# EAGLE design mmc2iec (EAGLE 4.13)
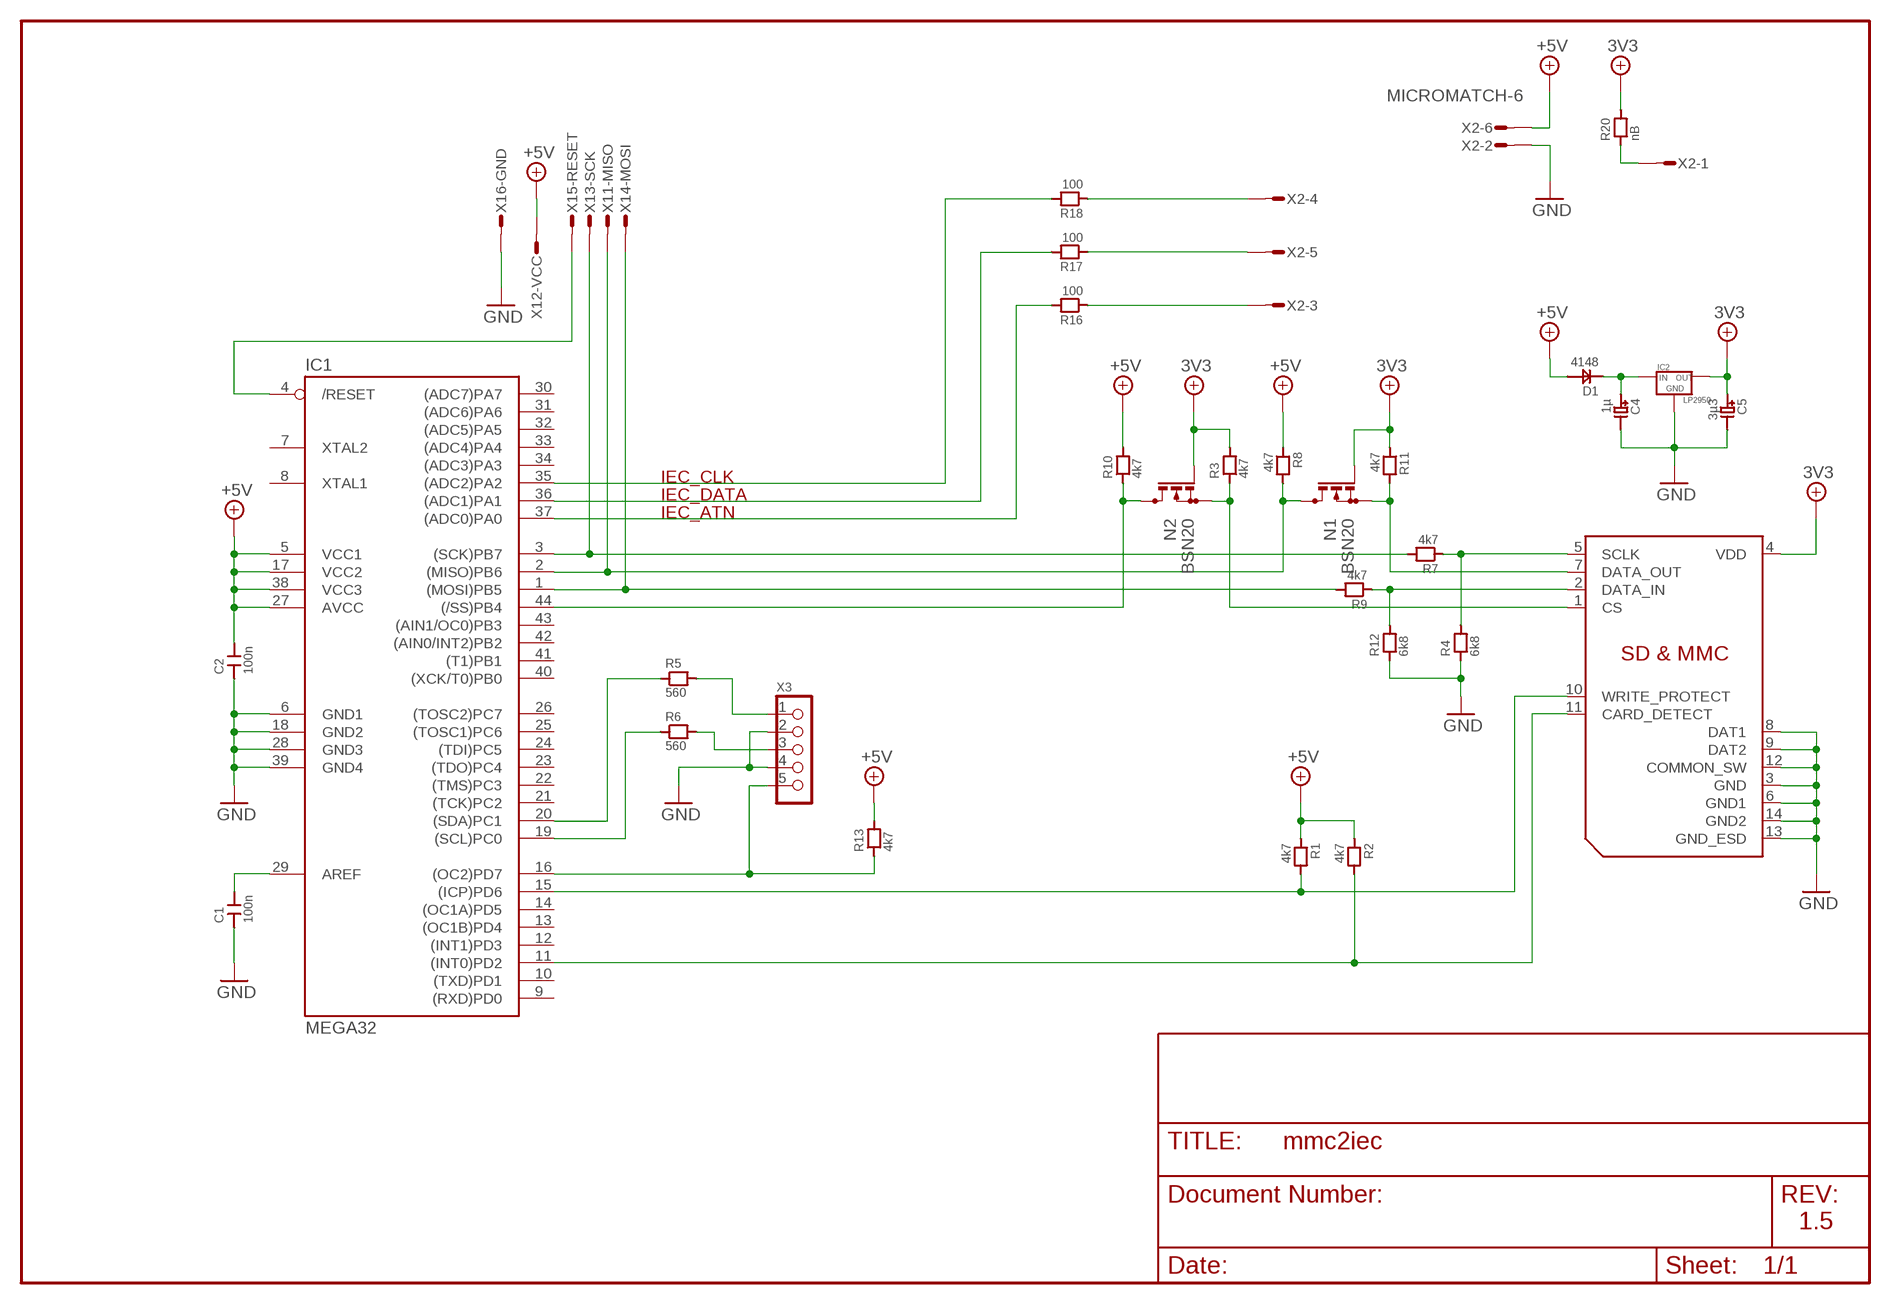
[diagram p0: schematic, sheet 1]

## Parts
C1  100n  C0805  [C0805]
C2  100n  C0805  [C0805]
C4  1µ  C_POLTA_A  [C_TANTAL_A]
C5  3µ3  C_POLTA_B  [C_TANTAL_B]
D1  4148  DSOD-123  [SOD-123]
IC1  MEGA32  MEGA16/32TQFP  [TQFP44]
IC2  LP2950  [TO92]
N1  BSN20  [SOT23]
N2  BSN20  [SOT23]
R1  4k7  R0805  [R0805]
R2  4k7  R0805  [R0805]
R3  4k7  R0805  [R0805]
R4  6k8  R0805  [R0805]
R5  560  R0805  [R0805]
R6  560  R0805  [R0805]
R7  4k7  R0805  [R0805]
R8  4k7  R0805  [R0805]
R9  4k7  R0805  [R0805]
R10  4k7  R0805  [R0805]
R11  4k7  R0805  [R0805]
R12  6k8  R0805  [R0805]
R13  4k7  R0805  [R0805]
R16  100  R0805  [R0805]
R17  100  R0805  [R0805]
R18  100  R0805  [R0805]
R20  nB  R0805  [R0805]
SD1  YAMAICHI_SD_MMC2305  [FPS009-2305]
X1  AVR-ISP_1X6  [1X6_ISP]
X2  MICROMATCH-6  [MICROMATCH-6]
X3  PINH1X5  [1X5]

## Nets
3V3: C5.1 IC2.3(OUT) N1.1(G) N2.1(G) R3.2 R11.1 R20.2 SD1.4(VDD)
+5V: C2.2 D1.2 IC1.5(VCC1) IC1.17(VCC2) IC1.27(AVCC) IC1.38(VCC3) R1.1 R2.1 R8.1 R10.2 R13.2 X1.2 X2.6
/RESET: IC1.4(/RESET) X1.5
ATN: IC1.37((ADC0)PA0) R16.2
CD: IC1.11((INT0)PD2) R2.2 SD1.11(CARD_DETECT)
CLK: IC1.35((ADC2)PA2) R18.2
DATA: IC1.36((ADC1)PA1) R17.2
GND: C1.1 C2.1 C4.2 C5.2 IC1.6(GND1) IC1.18(GND2) IC1.28(GND3) IC1.39(GND4) IC2.2(GND) R4.1 R12.1 SD1.3(GND) SD1.6(GND1) SD1.8(DAT1) SD1.9(DAT2) SD1.12(COMMON_SW) SD1.13(GND_ESD) SD1.14(GND2) X1.6 X2.2 X3.2 X3.4
MISO: IC1.2((MISO)PB6) N1.3(D) R8.2 X1.1
MOSI: IC1.1((MOSI)PB5) R9.2 X1.4
N$1: R20.1 X2.1
N$2: C4.1 D1.1 IC2.1(IN)
N$3: R4.2 R7.1 SD1.5(SCLK)
N$4: N1.2(S) R11.2 SD1.7(DATA_OUT)
N$5: R9.1 R12.2 SD1.2(DATA_IN)
N$6: IC1.44((/SS)PB4) N2.3(D) R10.1
N$7: R18.1 X2.4
N$8: R5.2 X3.1
N$9: R6.2 X3.3
N$10: IC1.16((OC2)PD7) R13.1 X3.5
N$11: R17.1 X2.5
N$12: R16.1 X2.3
N$18: C1.2 IC1.29(AREF)
PC0: IC1.19((SCL)PC0) R6.1
PC1: IC1.20((SDA)PC1) R5.1
SCK: IC1.3((SCK)PB7) R7.2 X1.3
SS: N2.2(S) R3.1 SD1.1(CS)
WP: IC1.15((ICP)PD6) R1.2 SD1.10(WRITE_PROTECT)
Unconnected: IC1.7(XTAL2) IC1.8(XTAL1) IC1.9((RXD)PD0) IC1.10((TXD)PD1) IC1.12((INT1)PD3) IC1.13((OC1B)PD4) IC1.14((OC1A)PD5) IC1.21((TCK)PC2) IC1.22((TMS)PC3) IC1.23((TDO)PC4) IC1.24((TDI)PC5) IC1.25((TOSC1)PC6) IC1.26((TOSC2)PC7) IC1.30((ADC7)PA7) IC1.31((ADC6)PA6) IC1.32((ADC5)PA5) IC1.33((ADC4)PA4) IC1.34((ADC3)PA3) IC1.40((XCK/T0)PB0) IC1.41((T1)PB1) IC1.42((AIN0/INT2)PB2) IC1.43((AIN1/OC0)PB3)

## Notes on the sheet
- IEC_CLK
- IEC_DATA
- IEC_ATN
- 1.5

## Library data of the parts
C1 C2 = 0_rr:C
C4 C5 = 0_rr:C_POL
D1 = 0_IAV:D
IC1 = 0_rr:MEGA16/32: MICROCONTROLLER 16 Kbytes FLASH, 512 bytes EEPROM 1 Kbytes SRAM dual UART hardware multiplier
IC2 = 0_rr:LP2950
N1 N2 = 0_rr:BSN20: N-CHANNEL MOS FET
R1-R3 R5-R11 R13 R16-R18 R20 = 0_rr:R
R4 R12 = 0_IAV:R
SD1 = 0_rr:YAMAICHI_SD_MMC
X1 = 0_rr:AVR-ISP: MicroMaTch 6 7-215464-6 / 0-215464-6 Drawing Number C-215464 DDEController.pdf
X2 = con-amp-micromatch:MICROMATCH-6: MicroMaTch 6 7-215464-6 / 0-215464-6 Drawing Number C-215464 DDEController.pdf
X3 = 0_rr:PINH1X5

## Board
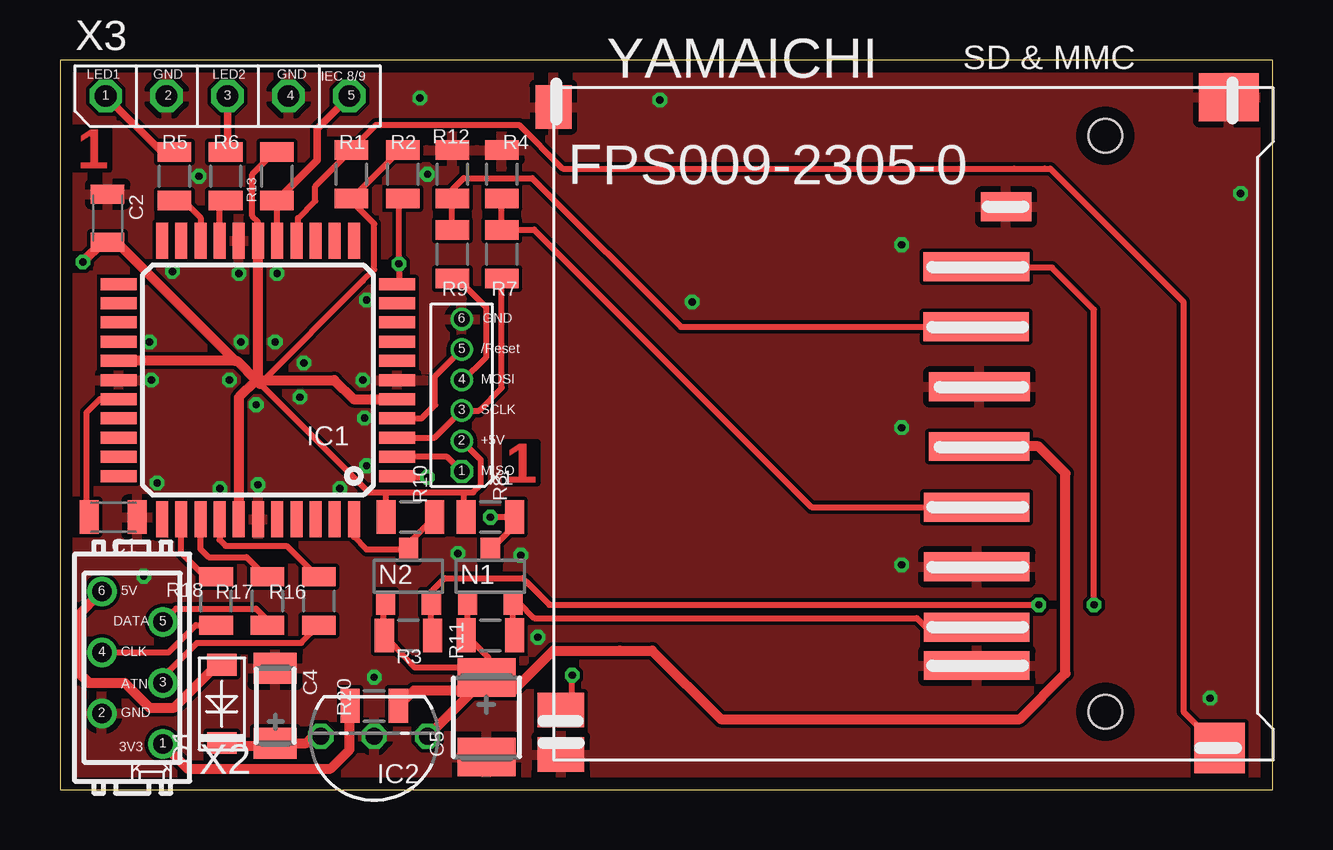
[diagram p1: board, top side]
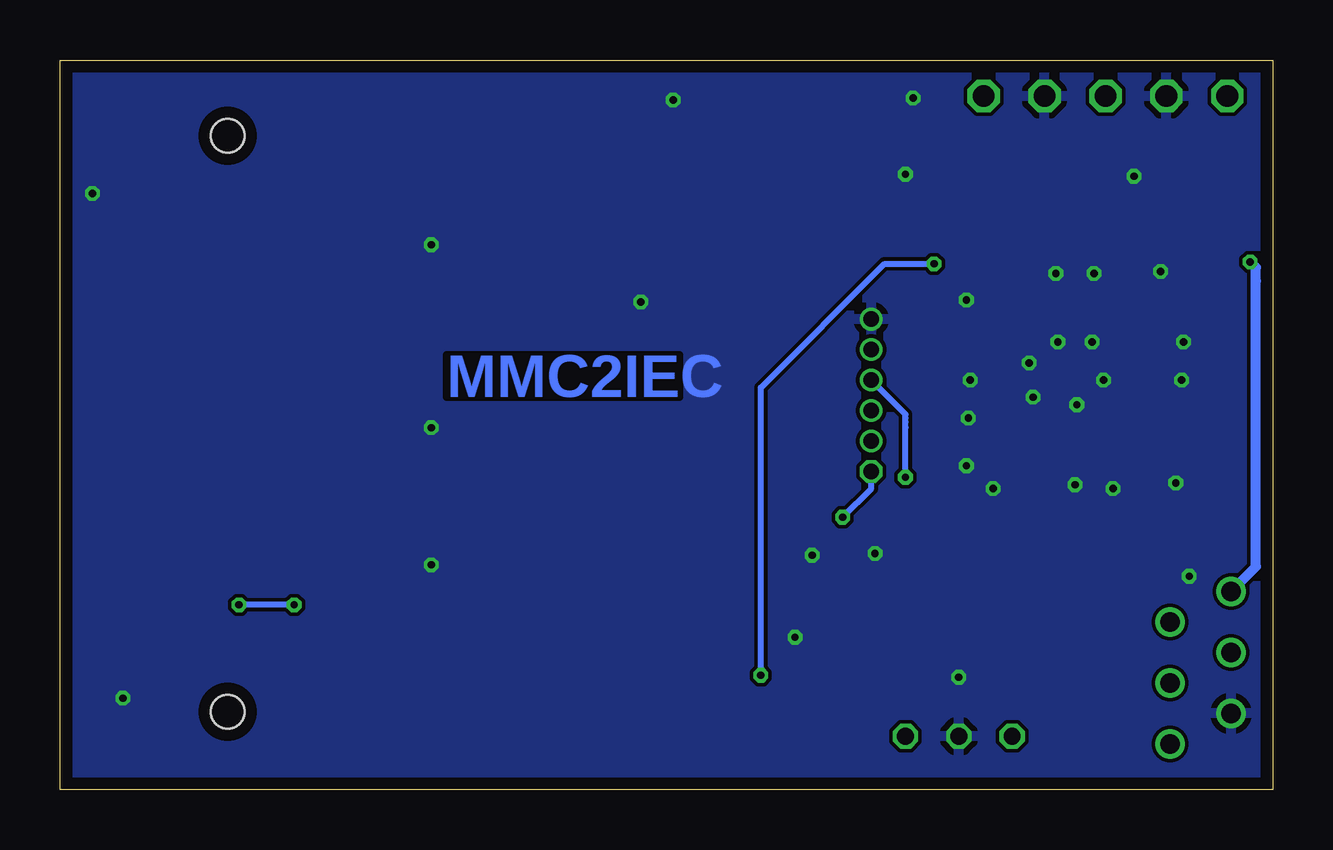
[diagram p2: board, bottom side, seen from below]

Size 50.56 x 30.4 mm. Coordinates in mm from the lower left corner, seen from the top.
Outline: 0,0 50.56,0 50.56,30.4 0,30.4 0,0
Copper layers (1*16): Top 0.035mm / dielectric 1.5mm / Bottom 0.035mm
Design rules "default": minimum track width 10mil, minimum drill 12mil, track to track 6mil, track to pad 6mil, pad to pad 6mil, via to via 6mil, smd to smd 6mil, copper to edge 20mil, drill to drill 8mil, minimum pad ring 6mil, minimum via ring 6mil, stop-mask expansion 4mil, vias tented up to drill 0mil, thermal gap 10mil

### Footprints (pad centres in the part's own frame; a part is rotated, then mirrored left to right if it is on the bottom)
C0805 = smd 0.8 x 1.4: 1 -1,0; 2 1,0
C_TANTAL_A = smd 1.3 x 1.8: 1 1.559,0; 2 -1.559,0
C_TANTAL_B = smd 1.6 x 2.4: 1 1.659,0; 2 -1.659,0
SOD-123 = smd 0.91 x 1.22: 1 -1.63,0; 2 1.63,0
TQFP44 = smd 1.5 x 0.5: 1 -5.8,4; 2 -5.8,3.2; 3 -5.8,2.4; 4 -5.8,1.6; 5 -5.8,0.8; 6 -5.8,0; 7 -5.8,-0.8; 8 -5.8,-1.6; 9 -5.8,-2.4; 10 -5.8,-3.2; 11 -5.8,-4; 23 5.8,-4; 24 5.8,-3.2; 25 5.8,-2.4; 26 5.8,-1.6; 27 5.8,-0.8; 28 5.8,0; 29 5.8,0.8; 30 5.8,1.6; 31 5.8,2.4; 32 5.8,3.2; 33 5.8,4 | smd 0.5 x 1.5: 12 -4,-5.8; 13 -3.2,-5.8; 14 -2.4,-5.8; 15 -1.6,-5.8; 16 -0.8,-5.8; 17 0,-5.8; 18 0.8,-5.8; 19 1.6,-5.8; 20 2.4,-5.8; 21 3.2,-5.8; 22 4,-5.8; 34 4,5.8; 35 3.2,5.8; 36 2.4,5.8; 37 1.6,5.8; 38 0.8,5.8; 39 0,5.8; 40 -0.8,5.8; 41 -1.6,5.8; 42 -2.4,5.8; 43 -3.2,5.8; 44 -4,5.8
TO92 = drill 0.7 octagon: 1 2.223,0; 2 0,0; 3 -2.223,0
SOT23 = smd 0.8 x 1: 1 -0.95,-1.1; 2 0.95,-1.1; 3 0,1.1
R0805 = smd 0.8 x 1.4: 1 -1.009,0; 2 1.009,0
FPS009-2305 = smd 4.4 x 1.2: 1 -5.38,6.54; 2 -5.39,4.04; 5 -5.36,-3.47; 6 -5.36,-5.96; 7 -5.36,-8.48; 8 -5.36,-10.07 | smd 4.2 x 1.2: 3 -5.25,1.54; 4 -5.26,-0.94 | smd 2.1 x 1.2: 9 -4.14,9.04 | smd 2.1 x 2.1: 10 4.75,-13.5 | smd 1.95 x 1.45: 11 -22.7,-11.92; 12 -22.7,-13.78 | smd 1.5 x 1.8: 13 -23.01,13.2 | smd 2.5 x 2: 14 5.15,13.6 | hole 1.4: 0,12; 0,-12
1X6_ISP = drill 0.635 pad 0.94 octagon: 1 0,0 | drill 0.635 pad 0.94 round: 2 1.27,0; 3 2.54,0; 4 3.81,0; 5 5.08,0; 6 6.35,0
MICROMATCH-6 = drill 0.813 round: 1 3.175,1.27; 2 1.905,-1.27; 3 0.635,1.27; 4 -0.635,-1.27; 5 -1.905,1.27; 6 -3.175,-1.27
1X5 = drill 0.9 octagon: 1 -5.08,0; 2 -2.54,0; 3 0,0; 4 2.54,0; 5 5.08,0

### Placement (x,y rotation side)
C1  2.22,11.35 180 top
C2  1.98,23.81 270 top
C4  8.97,3.49 270 top
C5  17.78,3.02 90 top
D1  6.75,3.57 90 top
IC1  8.26,17.07 180 top
IC2  13.1,2.22 180 top
N1  17.94,8.89 0 top
N2  14.53,8.89 0 top
R1  12.14,25.64 90 top
R2  14.29,25.64 270 top
R3  14.53,6.43 180 top
R4  18.42,25.64 270 top
R5  4.76,25.56 90 top
R6  6.91,25.56 90 top
R7  18.42,22.3 270 top
R8  17.94,11.35 0 top
R9  16.35,22.3 270 top
R10  14.61,11.35 180 top
R11  17.94,6.43 0 top
R12  16.35,25.64 270 top
R13  9.05,25.56 90 top
R16  10.8,7.86 90 top
R17  8.65,7.86 90 top
R18  6.51,7.86 90 top
R20  13.1,3.49 0 top
SD1  43.58,15.24 0 top
X1  16.75,13.26 90 top
X2  3.02,5.08 270 top
X3  6.99,28.89 0 top

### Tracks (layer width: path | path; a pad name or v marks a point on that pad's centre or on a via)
3V3
  Top 0.254: 13.49,6.33 13.49,6.19 | 13.49,6.33 R3.2 14.79,5.08 16.67,5.08 17.62,4.21 17.93,4.21 C5.1 17.86,4.28 17.86,4.37 17.86,5.5 R11.1 16.99,6.29 | N2.1 13.49,7.71 13.49,6.33 | 16.99,6.29 16.99,6.19 | N1.1 16.99,6.29
  Top 0.305: 17.94,4.05 17.94,4.13 17.94,4.52 C5.1
  Top 0.406: SD1.4 40.79,14.3 41.91,13.18 41.91,4.84 40.01,2.94 27.54,2.94 24.69,5.79 23.34,5.8 20.56,5.8 18.89,4.13 17.94,4.13 | 17.94,4.13 | C5.1 17.94,4.13 | 17.94,4.13 17.94,4.2 C5.1 | R20.2 14.74,4.13 17.94,4.13 | C5.1 17.86,4.37 C5.1 IC2.3 | IC2.3
+5V  (via drill 0.3)
  Top 0.254: 12.62,21.19 | 12.62,21.19 8.33,16.91 12.86,12.38 13.57,12.38 | IC1.17 | IC1.17 | IC1.17 8.26,23.65 8.02,23.89 8.02,25.64 8.97,26.59 8.99,26.57 R13.2 | 12.14,24.61 | R1.1 12.14,24.61 | R2.1 14.19,26.65 12.14,24.61 | R1.1 12.14,24.53 | 12.06,24.61 12.12,24.61 R1.1 | 12.62,21.19 13.1,21.67 13.1,23.57 12.14,24.53 | 12.14,24.53 R1.1 | R1.1 | X1.2 17.54,13.73 17.54,12.7 17.22,12.38 16.83,12.38 | 13.57,12.38 16.83,12.38 | R10.2 13.57,11.37 13.57,12.38 | R8.1 16.83,11.45 16.83,12.38
  Top 0.406: IC1.27 7.3,17.86 | 8.26,16.99 8.33,16.91 | 8.18,17.07 8.26,16.99 | 8.18,17.07 7.38,17.86 7.3,17.86 | IC1.17 | 8.26,16.99 8.26,17.15 | 8.26,17.15 IC1.17 | IC1.38 7.46,16.35 8.18,17.07 | 8.18,17.07 8.26,17.15 | IC1.5 12.23,16.27 11.43,17.07 8.18,17.07 | D1.2 6.55,5.2 4.76,3.41 3.73,3.41 2.7,4.45 1.19,4.45 0.71,4.92 0.71,7.22 X2.6 | X2.6 | X2.6 | C2.2 1.78,22.81 v0.95,21.99 | C2.2 1.98,22.78 2.38,22.78 7.3,17.86 | C2.2
  Bottom 0.406: X2.6 | v0.95,21.99 0.71,21.75 0.71,21.19 0.71,9.29 X2.6
/RESET
  Top 0.254: IC1.4 15.07,15.47 15.64,16.03 15.64,17.22 X1.5 | X1.5
ATN
  Top 0.254: IC1.37 6.66,10.41 6.91,10.16 9.45,10.16 10.79,8.81 | 10.79,8.81 | 10.79,8.81 R16.2
CD  (via drill 0.3)
  Top 0.254: SD1.11 21.35,3.26 21.35,3.25 v21.35,4.76 | R2.2 14.29,24.61 14.13,24.45 v14.13,21.91 14.13,21.11 14.1,21.11 IC1.11
  Bottom 0.254: v21.35,4.76 21.35,8.26 21.35,13.41 21.35,15.4 21.35,16.75 16.19,21.91 v14.13,21.91
CLK
  Top 0.254: R18.2 6.06,8.87 5.05,9.87 IC1.35
DATA
  Top 0.254: IC1.36 5.86,10.02 6.19,9.68 7.78,9.68 8.65,8.81 | 8.65,8.81 | 8.65,8.81 R17.2
GND  (via drill 0.3)
  other vias: 25,28.73 9.05,21.51 12.62,17.07 12.7,15.48 7.46,21.51 3.81,17.07 7.06,17.07 12.78,20.4 11.67,12.54 8.26,12.7 6.67,12.54 4.05,12.78 35.08,9.37 35.08,15.08 35.08,22.7 49.21,24.84 8.97,18.65 7.54,18.65 3.73,18.65 4.68,21.59 10.16,17.78 8.18,16.03 10,16.35 12.78,13.49 47.94,3.81 19.21,9.76 16.59,9.84 13.1,4.68 19.92,6.35 15.32,25.64 26.35,20.32 15,28.81 5.79,25.56 3.49,8.89
  pour Top: 0,0 0,30.4 50.56,30.4 50.56,0
  pour Bottom: 0,0 0,30.4 50.56,30.4 50.56,0
MISO  (via drill 0.3)
  Top 0.254: v17.94,11.35 R8.2 18.97,11.35 18.97,11.02 N1.3 | v17.94,11.35 | X1.1 | IC1.2 16.14,13.87 X1.1
  Bottom 0.254: X1.1 | v17.94,11.35 16.75,12.54 X1.1
MOSI  (via drill 0.3)
  Top 0.254: IC1.1 14.1,13.02 v15.32,13.02 | R9.2 16.57,21.3 17.78,20.08 17.78,18.02 16.75,16.99 | 16.75,16.99 | X1.4 16.75,16.99
  Bottom 0.254: X1.4 15.32,15.64 15.32,15.48 15.32,15.32 15.32,15.08 v15.32,13.02
N$1
  Top 0.406: X2.1 5.32,0.87 11.27,0.87 12.06,1.67 12.06,3.49 R20.1
N$2
  Top 0.406: D1.1 6.79,1.83 8.92,1.83 C4.1 10.27,1.93 10.56,2.22 IC2.1
N$3
  Top 0.254: SD1.5 31.33,11.77 19.76,23.34 18.41,23.34 | 18.41,23.34 18.34,23.42 | 18.41,23.34 18.42,23.34 R7.1 | R4.2 18.41,23.34
N$4
  Top 0.254: 38.23,6.75 38.26,6.75 | 38.23,6.75 SD1.7 | 38.23,6.75 36.12,6.75 35.72,7.14 19.76,7.14 19.13,7.78 N1.2 18.89,6.41 R11.2
N$5
  Top 0.254: R9.1 16.35,23.16 16.35,24.79 R12.2 16.35,25 16.83,25.48 19.68,25.48 25.88,19.28 SD1.2
N$6
  Top 0.254: R10.1 14.53,10.26 N2.3 | IC1.44 12.26,10.53 12.78,10 N2.3 | N2.3
N$7
  Top 0.254: R18.1 5.66,6.85 4.52,5.72 X2.4 | X2.4
N$8
  Top 0.305: R5.2 4.23,26.57 X3.1
N$9
  Top 0.254: R6.2
  Top 0.305: R6.2 6.99,26.65 X3.3
N$10
  Top 0.254: R13.1 9.05,24.53 9.05,24.52 IC1.16
  Top 0.305: R13.1 10.72,26.22 10.72,27.54 X3.5
N$11
  Top 0.254: X2.5 4.84,7.54 8.18,7.54 8.65,7.06 R17.1
N$12
  Top 0.254: R16.1 10.06,6.11 5.71,6.11 4.29,4.68 X2.3 | X2.3
N$18
  Top 0.254: IC1.29 1.66,16.27 1.11,15.72 1.11,11.59 1.11,11.43 C1.2
PC0
  Top 0.254: R6.1 6.85,24.55 6.66,24.36 IC1.19
PC1
  Top 0.254: R5.1 5.14,24.55 5.86,23.83 IC1.20
SCK
  Top 0.254: X1.3 | IC1.3 15.62,14.67 X1.3 | X1.3 17.46,15.8 18.41,16.75 18.41,21.27 18.42,21.27 R7.2
SS  (via drill 0.3)
  Top 0.254: v40.8,7.7 20.4,7.7 19.53,8.57 19.29,8.81 16.03,8.81 15.48,8.25 N2.2 15.48,6.41 R3.1 | v43.1,7.7 43.1,20 41.35,21.75 38.1,21.75 38.13,21.78 SD1.1
  Bottom 0.254: v40.8,7.7 v43.1,7.7
WP
  Top 0.254: SD1.10 48.33,1.76 46.83,3.25 46.83,20.32 41.27,25.88 41.04,25.88 39.77,25.88 20.95,25.88 19.13,27.7 13.18,27.7 12.14,26.67 R1.2 10.64,25.14 10.64,24.53 9.92,23.81 9.92,22.93 IC1.15

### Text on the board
Top: 1 | 1
Bottom: MMC2IEC
tPlace: LED1 | GND | LED2 | GND | IEC 8/9 | 1 | 2 | 3 | 4 | 5 | 6 | GND | 5 | /Reset | 4 | MOSI | 3 | SCLK | 2 | +5V | 1 | MISO | 6 | 5V | DATA | 5 | 4 | CLK | ATN | 3 | 2 | GND | 3V3 | 1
